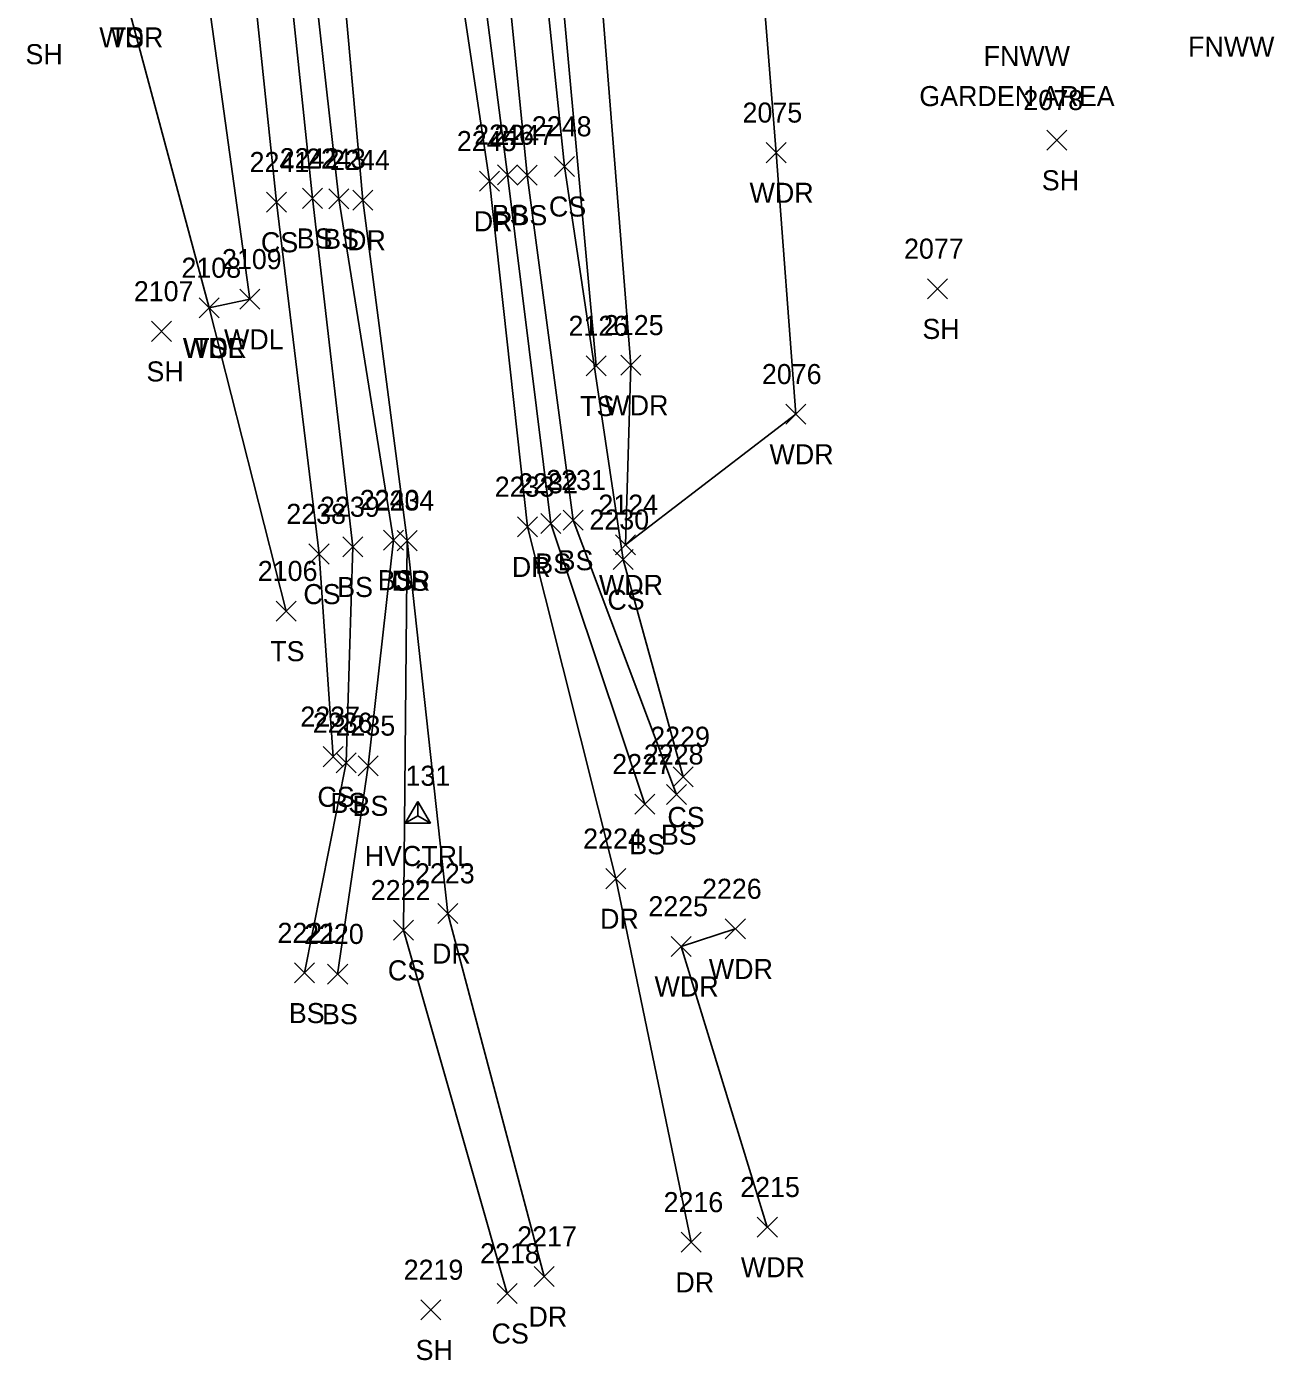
# Model space of a CAD drawing. Extents: x 1761340 to 1763889, y 696770 to 706023.
# Drawn here: x 1761619.7 to 1761744, y 700530.1 to 700663 of the extents above; entities that cross this region are included whole.
import ezdxf

# ---------------------------------------------------------------- set-up
doc = ezdxf.new("R2010")
doc.units = 0
for name, color, linetype in [('C_A', 7, 'Continuous'), ('C_I', 7, 'Continuous'), ('CPSM', 7, 'Continuous'), ('L_A', 7, 'Continuous'), ('L_C', 7, 'Continuous'), ('L_I', 7, 'Continuous'), ('L_TIC', 7, 'Continuous'), ('LAWA', 7, 'Continuous'), ('LELB', 7, 'Continuous'), ('R_A', 7, 'Continuous'), ('R_I', 7, 'Continuous'), ('R_TIC', 7, 'Continuous'), ('RDP', 7, 'Continuous')]:
    doc.layers.add(name, color=color, linetype=linetype)

msp = doc.modelspace()

# ---------------------------------------------------------------- linework, layer by layer
at = {"layer": 'CPSM'}
for p, q in [((1761657.41, 700583.62), (1761658.66, 700585.79)), ((1761659.91, 700583.62), (1761658.66, 700585.79)), ((1761658.66, 700584.35), (1761658.66, 700585.79)), ((1761657.41, 700583.62), (1761658.66, 700584.35)), ((1761658.66, 700584.35), (1761658.66, 700584.35)), ((1761658.66, 700584.35), (1761659.91, 700583.62)), ((1761657.41, 700583.62), (1761659.91, 700583.62))]:
    msp.add_line(p, q, dxfattribs=at)
at = {"layer": 'L_TIC'}
for points in [[(1761721.37, 700650.72), (1761723.37, 700652.72)], [(1761723.37, 700650.72), (1761721.37, 700652.72)], [(1761693.37, 700649.47), (1761695.37, 700651.47)], [(1761695.37, 700649.47), (1761693.37, 700651.47)], [(1761672.29, 700648.1), (1761674.29, 700650.1)], [(1761674.29, 700648.1), (1761672.29, 700650.1)], [(1761666.59, 700647.27), (1761668.59, 700649.27)], [(1761668.59, 700647.27), (1761666.59, 700649.27)], [(1761668.56, 700647.24), (1761670.56, 700649.24)], [(1761670.56, 700647.24), (1761668.56, 700649.24)], [(1761647.15, 700644.92), (1761649.15, 700646.92)], [(1761649.15, 700644.92), (1761647.15, 700646.92)], [(1761649.78, 700644.88), (1761651.78, 700646.88)], [(1761651.78, 700644.88), (1761649.78, 700646.88)], [(1761643.58, 700644.54), (1761645.58, 700646.54)], [(1761645.58, 700644.54), (1761643.58, 700646.54)], [(1761709.47, 700635.9), (1761711.47, 700637.9)], [(1761711.47, 700635.9), (1761709.47, 700637.9)], [(1761640.92, 700634.86), (1761642.92, 700636.86)], [(1761642.92, 700634.86), (1761640.92, 700636.86)], [(1761636.87, 700634), (1761638.87, 700636)], [(1761638.87, 700634), (1761636.87, 700636)], [(1761636.87, 700634), (1761638.87, 700636)], [(1761638.87, 700634), (1761636.87, 700636)], [(1761636.87, 700634), (1761638.87, 700636)], [(1761638.87, 700634), (1761636.87, 700636)], [(1761632.12, 700631.66), (1761634.12, 700633.66)], [(1761634.12, 700631.66), (1761632.12, 700633.66)], [(1761675.43, 700628.21), (1761677.43, 700630.21)], [(1761677.43, 700628.21), (1761675.43, 700630.21)], [(1761678.9, 700628.28), (1761680.9, 700630.28)], [(1761680.9, 700628.28), (1761678.9, 700630.28)], [(1761695.35, 700623.4), (1761697.35, 700625.4)], [(1761697.35, 700623.4), (1761695.35, 700625.4)], [(1761673.15, 700612.84), (1761675.15, 700614.84)], [(1761675.15, 700612.84), (1761673.15, 700614.84)], [(1761670.93, 700612.51), (1761672.93, 700614.51)], [(1761672.93, 700612.51), (1761670.93, 700614.51)], [(1761651.18, 700610.17), (1761653.18, 700612.17)], [(1761653.18, 700610.17), (1761651.18, 700612.17)], [(1761655.23, 700610.85), (1761657.23, 700612.85)], [(1761657.23, 700610.85), (1761655.23, 700612.85)], [(1761656.61, 700610.79), (1761658.61, 700612.79)], [(1761658.61, 700610.79), (1761656.61, 700612.79)], [(1761678.35, 700610.38), (1761680.35, 700612.38)], [(1761680.35, 700610.38), (1761678.35, 700612.38)], [(1761647.81, 700609.46), (1761649.81, 700611.46)], [(1761649.81, 700609.46), (1761647.81, 700611.46)], [(1761678.12, 700608.9), (1761680.12, 700610.9)], [(1761680.12, 700608.9), (1761678.12, 700610.9)], [(1761644.54, 700603.77), (1761646.54, 700605.77)], [(1761646.54, 700603.77), (1761644.54, 700605.77)], [(1761649.21, 700589.25), (1761651.21, 700591.25)], [(1761651.21, 700589.25), (1761649.21, 700591.25)], [(1761650.51, 700588.64), (1761652.51, 700590.64)], [(1761652.51, 700588.64), (1761650.51, 700590.64)], [(1761652.72, 700588.35), (1761654.72, 700590.35)], [(1761654.72, 700588.35), (1761652.72, 700590.35)], [(1761684.1, 700587.24), (1761686.1, 700589.24)], [(1761686.1, 700587.24), (1761684.1, 700589.24)], [(1761683.45, 700585.47), (1761685.45, 700587.47)], [(1761685.45, 700585.47), (1761683.45, 700587.47)], [(1761680.3, 700584.52), (1761682.3, 700586.52)], [(1761682.3, 700584.52), (1761680.3, 700586.52)], [(1761656.23, 700571.95), (1761658.23, 700573.95)], [(1761658.23, 700571.95), (1761656.23, 700573.95)], [(1761689.31, 700572.08), (1761691.31, 700574.08)], [(1761691.31, 700572.08), (1761689.31, 700574.08)], [(1761683.9, 700570.34), (1761685.9, 700572.34)], [(1761685.9, 700570.34), (1761683.9, 700572.34)], [(1761646.36, 700567.69), (1761648.36, 700569.69)], [(1761648.36, 700567.69), (1761646.36, 700569.69)], [(1761649.67, 700567.58), (1761651.67, 700569.58)], [(1761651.67, 700567.58), (1761649.67, 700569.58)], [(1761692.5, 700542.35), (1761694.5, 700544.35)], [(1761694.5, 700542.35), (1761692.5, 700544.35)], [(1761666.57, 700535.74), (1761668.57, 700537.74)], [(1761668.57, 700535.74), (1761666.57, 700537.74)], [(1761658.95, 700534.1), (1761660.95, 700536.1)], [(1761660.95, 700534.1), (1761658.95, 700536.1)]]:
    msp.add_lwpolyline(points, dxfattribs=at)
at = {"layer": 'LAWA'}
for points in [[(1761713.14, 700758.3), (1761701.74, 700731.81), (1761691.69, 700708.02), (1761692.15, 700678.39), (1761694.37, 700650.47), (1761696.35, 700624.4)], [(1761679.35, 700611.38), (1761679.9, 700629.28), (1761676.41, 700673.21), (1761675.31, 700690.44), (1761672.48, 700724.21)], [(1761637.87, 700635), (1761629.55, 700665.96), (1761637.46, 700668.1)], [(1761637.87, 700635), (1761641.92, 700635.86), (1761637.46, 700668.1)], [(1761696.35, 700624.4), (1761679.35, 700611.38)], [(1761693.5, 700543.35), (1761684.9, 700571.34), (1761690.31, 700573.08)]]:
    msp.add_lwpolyline(points, dxfattribs=at)
at = {"layer": 'LELB'}
for points in [[(1761681.3, 700585.52), (1761671.93, 700613.51), (1761667.59, 700648.27), (1761662.96, 700684.4), (1761660.97, 700720.86), (1761660.49, 700762.08), (1761662.81, 700791.59), (1761666.16, 700822.15), (1761669.09, 700835.75), (1761669.55, 700847.22), (1761671.38, 700859.7), (1761679.65, 700896.38), (1761688.23, 700933.04), (1761696.4, 700960.96), (1761706.35, 700997.91), (1761723.36, 701026.16)], [(1761684.45, 700586.47), (1761674.15, 700613.84), (1761669.56, 700648.24), (1761665.94, 700684.58), (1761663.69, 700720.73), (1761662.67, 700762.27), (1761665.11, 700791.25), (1761666.95, 700822.18), (1761669.97, 700835.61), (1761670.38, 700847.09), (1761671.95, 700859.51), (1761680.67, 700895.81), (1761689.74, 700932.61), (1761697.72, 700961.08), (1761707.94, 700997.33), (1761724.65, 701022.11)], [(1761650.67, 700568.58), (1761653.72, 700589.35), (1761656.23, 700611.85), (1761650.78, 700645.88), (1761646.69, 700682.27), (1761643.97, 700721.14), (1761646.18, 700763.15), (1761649, 700791.97), (1761651.08, 700826.68), (1761655.56, 700862.86), (1761665.44, 700900.35), (1761673.53, 700937.72), (1761682.38, 700964.35), (1761693, 701008.08), (1761690.13, 701015.34), (1761683.01, 701019.11)], [(1761647.36, 700568.69), (1761651.51, 700589.64), (1761652.18, 700611.17), (1761648.15, 700645.92), (1761644.28, 700683.03), (1761641.56, 700721.37), (1761643.75, 700763.66), (1761644.59, 700792.45), (1761648.47, 700827.4), (1761652.74, 700863.51), (1761659.58, 700901.67), (1761670.1, 700938.53), (1761679.51, 700964.49), (1761691.19, 701008.19), (1761682.17, 701016.5)], [(1761650.21, 700590.25), (1761648.81, 700610.46), (1761644.58, 700645.54), (1761640.71, 700682.5), (1761639.82, 700689.73), (1761639.14, 700693.98), (1761637.85, 700721.72), (1761639.72, 700763.34), (1761641.24, 700792.73), (1761643.28, 700816.47), (1761646.04, 700834.75), (1761651.11, 700867.03), (1761649.91, 700870.22), (1761650.05, 700873.46)], [(1761685.1, 700588.24), (1761679.12, 700609.9), (1761673.29, 700649.1), (1761669.6, 700684.44), (1761667.58, 700720.71), (1761666.68, 700761.34), (1761668.83, 700791.97), (1761671.15, 700812.18), (1761668.52, 700820.34)], [(1761676.43, 700629.21), (1761672.54, 700671.9), (1761672.28, 700690.3), (1761672.48, 700724.21)], [(1761645.54, 700604.77), (1761637.87, 700635)], [(1761667.57, 700536.74), (1761657.23, 700572.95), (1761657.61, 700611.79)]]:
    msp.add_lwpolyline(points, dxfattribs=at)
at = {"layer": 'R_TIC'}
for points in [[(1761664.81, 700646.63), (1761666.81, 700648.63)], [(1761666.81, 700646.63), (1761664.81, 700648.63)], [(1761652.18, 700644.74), (1761654.18, 700646.74)], [(1761654.18, 700644.74), (1761652.18, 700646.74)], [(1761668.59, 700612.17), (1761670.59, 700614.17)], [(1761670.59, 700612.17), (1761668.59, 700614.17)], [(1761656.61, 700610.79), (1761658.61, 700612.79)], [(1761658.61, 700610.79), (1761656.61, 700612.79)], [(1761677.4, 700577.09), (1761679.4, 700579.09)], [(1761679.4, 700577.09), (1761677.4, 700579.09)], [(1761660.64, 700573.62), (1761662.64, 700575.62)], [(1761662.64, 700573.62), (1761660.64, 700575.62)], [(1761684.9, 700540.84), (1761686.9, 700542.84)], [(1761686.9, 700540.84), (1761684.9, 700542.84)], [(1761670.26, 700537.43), (1761672.26, 700539.43)], [(1761672.26, 700537.43), (1761670.26, 700539.43)]]:
    msp.add_lwpolyline(points, dxfattribs=at)
at = {"layer": 'RDP'}
for points in [[(1761671.26, 700538.43), (1761661.64, 700574.62), (1761657.61, 700611.79), (1761653.18, 700645.74), (1761649.93, 700682.03), (1761646.9, 700721.23), (1761649.1, 700763.06), (1761651.35, 700791.61), (1761653.66, 700826.22), (1761659.48, 700861.88), (1761668.31, 700899.37), (1761676.77, 700936.6), (1761684.87, 700963.93), (1761695.51, 701007.43), (1761695.75, 701009.14), (1761702.96, 701038.72), (1761714.69, 701083.39), (1761730.25, 701133.73)], [(1761685.9, 700541.84), (1761678.4, 700578.09), (1761669.59, 700613.17), (1761665.81, 700647.63), (1761660.31, 700684.32), (1761659.55, 700721.03), (1761658.73, 700762.09), (1761660.8, 700791.69), (1761663.62, 700822.45), (1761666.15, 700836.34), (1761667.52, 700847.08), (1761668.95, 700859.68), (1761676.88, 700896.8), (1761686.16, 700933.2), (1761693.93, 700961.97), (1761704.59, 700998.32), (1761705.06, 700999.04), (1761715.84, 701034.88), (1761727.08, 701077.74), (1761742.29, 701129.68)]]:
    msp.add_lwpolyline(points, dxfattribs=at)

# ---------------------------------------------------------------- texts
at = {"layer": 'C_A'}
msp.add_text('HVCTRL', height=2, dxfattribs=at).set_placement((1761653.36, 700579.35))
at = {"layer": 'C_I'}
msp.add_text('131', height=2, dxfattribs=at).set_placement((1761657.43, 700587.35))
at = {"layer": 'L_A'}
for s, p in [('WDR', (1761626.91, 700660.96)), ('TS', (1761627.95, 700660.96)), ('FNWW', (1761735.44, 700660.05)), ('FNWW', (1761735.44, 700660.05)), ('SH', (1761619.55, 700659.29)), ('FNWW', (1761715.06, 700659.11)), ('FNWW', (1761715.06, 700659.11)), ('SH', (1761720.86, 700646.72)), ('WDR', (1761691.73, 700645.47)), ('CS', (1761671.73, 700644.1)), ('BS', (1761666.03, 700643.27)), ('BS', (1761668, 700643.24)), ('BS', (1761646.59, 700640.92)), ('BS', (1761649.22, 700640.88)), ('CS', (1761643.02, 700640.54)), ('SH', (1761708.96, 700631.9)), ('WDL', (1761639.34, 700630.86)), ('WDR', (1761635.23, 700630)), ('WDL', (1761635.28, 700630)), ('TS', (1761636.28, 700630)), ('SH', (1761631.61, 700627.66)), ('TS', (1761674.84, 700624.21)), ('WDR', (1761677.26, 700624.28)), ('WDR', (1761693.72, 700619.4)), ('BS', (1761672.6, 700608.84)), ('BS', (1761670.37, 700608.51)), ('BS', (1761650.62, 700606.17)), ('BS', (1761654.67, 700606.85)), ('CS', (1761656.05, 700606.79)), ('WDR', (1761676.71, 700606.38)), ('CS', (1761647.25, 700605.46)), ('CS', (1761677.56, 700604.9)), ('TS', (1761643.95, 700599.77)), ('CS', (1761648.65, 700585.25)), ('BS', (1761649.95, 700584.64)), ('BS', (1761652.16, 700584.35)), ('CS', (1761683.54, 700583.24)), ('BS', (1761682.89, 700581.47)), ('BS', (1761679.74, 700580.52)), ('CS', (1761655.67, 700567.95)), ('WDR', (1761687.67, 700568.08)), ('WDR', (1761682.26, 700566.34)), ('BS', (1761645.8, 700563.69)), ('BS', (1761649.11, 700563.58)), ('WDR', (1761690.86, 700538.35)), ('CS', (1761666.01, 700531.74)), ('SH', (1761658.44, 700530.1))]:
    msp.add_text(s, height=2, dxfattribs=at).set_placement(p)
at = {"layer": 'L_C'}
msp.add_text('GARDEN AREA', height=2, dxfattribs=at).set_placement((1761708.65, 700655.11))
msp.add_text('GARDEN AREA', height=2, dxfattribs=at).set_placement((1761708.65, 700655.11))
at = {"layer": 'L_I'}
for s, p in [('2078', (1761719.03, 700654.72)), ('2075', (1761691.03, 700653.47)), ('2248', (1761670.03, 700652.1)), ('2246', (1761664.28, 700651.27)), ('2247', (1761666.3, 700651.24)), ('2242', (1761644.89, 700648.92)), ('2243', (1761647.52, 700648.88)), ('2241', (1761641.89, 700648.54)), ('2077', (1761707.13, 700639.9)), ('2109', (1761639.14, 700638.86)), ('2108', (1761635.1, 700638)), ('2108', (1761635.1, 700638)), ('2108', (1761635.1, 700638)), ('2107', (1761630.35, 700635.66)), ('2126', (1761673.68, 700632.21)), ('2125', (1761677.21, 700632.28)), ('2076', (1761692.96, 700627.4)), ('2231', (1761671.46, 700616.84)), ('2232', (1761668.67, 700616.51)), ('2239', (1761648.91, 700614.17)), ('2240', (1761652.88, 700614.85)), ('2234', (1761654.35, 700614.79)), ('2124', (1761676.66, 700614.38)), ('2238', (1761645.55, 700613.46)), ('2230', (1761675.77, 700612.9)), ('2106', (1761642.71, 700607.77)), ('2237', (1761646.95, 700593.25)), ('2236', (1761648.19, 700592.64)), ('2235', (1761650.46, 700592.35)), ('2229', (1761681.83, 700591.24)), ('2228', (1761681.19, 700589.47)), ('2227', (1761678.04, 700588.52)), ('2222', (1761653.97, 700575.95)), ('2226', (1761686.99, 700576.08)), ('2225', (1761681.64, 700574.34)), ('2221', (1761644.67, 700571.69)), ('2220', (1761647.32, 700571.58)), ('2215', (1761690.8, 700546.35)), ('2218', (1761664.87, 700539.74)), ('2219', (1761657.25, 700538.1))]:
    msp.add_text(s, height=2, dxfattribs=at).set_placement(p)
at = {"layer": 'R_A'}
for p in [(1761664.24, 700642.63), (1761651.61, 700640.74), (1761668.03, 700608.17), (1761656.04, 700606.79), (1761676.83, 700573.09), (1761660.08, 700569.62), (1761684.34, 700536.84), (1761669.69, 700533.43)]:
    msp.add_text('DR', height=2, dxfattribs=at).set_placement(p)
at = {"layer": 'R_I'}
for s, p in [('2245', (1761662.55, 700650.63)), ('2244', (1761649.92, 700648.74)), ('2233', (1761666.33, 700616.17)), ('2234', (1761654.35, 700614.79)), ('2224', (1761675.14, 700581.09)), ('2223', (1761658.38, 700577.62)), ('2216', (1761683.16, 700544.84)), ('2217', (1761668.57, 700541.43))]:
    msp.add_text(s, height=2, dxfattribs=at).set_placement(p)

doc.saveas('drawing.dxf')
